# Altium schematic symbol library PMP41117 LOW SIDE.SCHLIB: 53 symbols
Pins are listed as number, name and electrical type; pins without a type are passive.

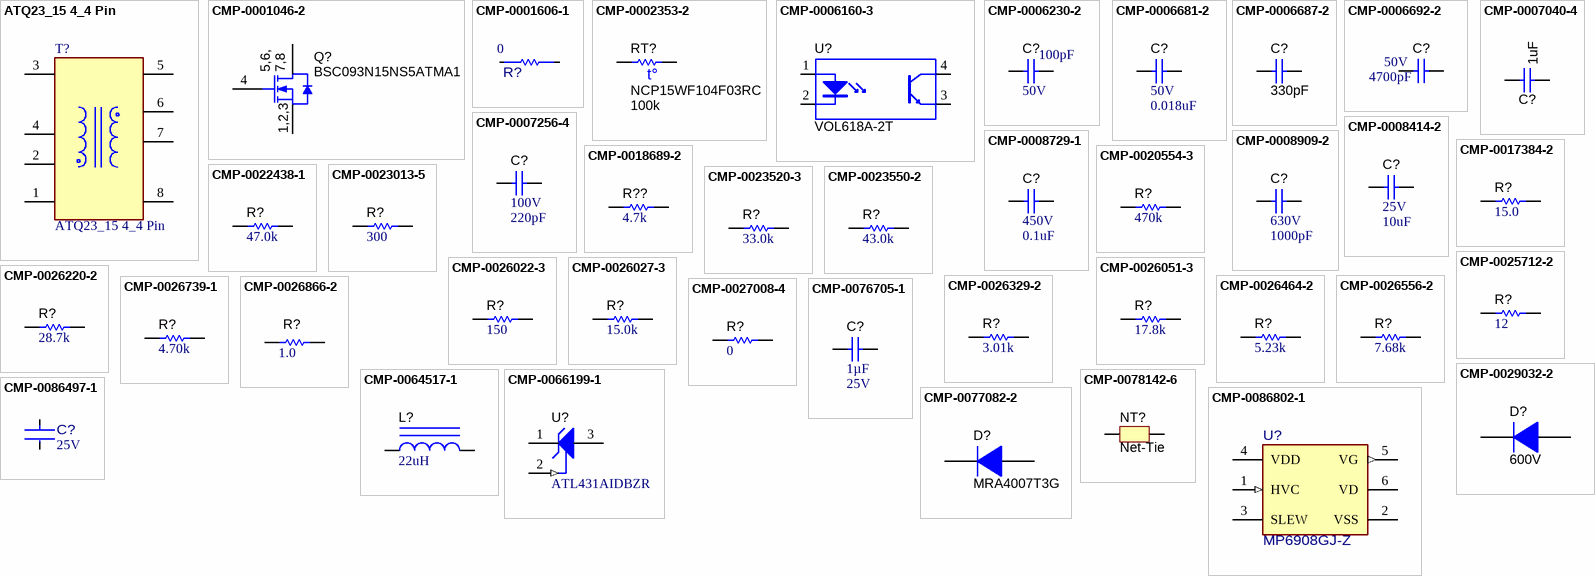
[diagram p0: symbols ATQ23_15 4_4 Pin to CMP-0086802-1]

## ATQ23_15 4_4 Pin
designator T?
footprint ATQ23.7_15 4+4 Pin
pins: 1, 2, 3, 4, 5, 6, 7, 8

## CMP-0001046-2
designator Q?, comment BSC093N15NS5ATMA1
MOSFET, N-CH, 150 V, 87 A, PG-TDSON-8; Alternate Manufacturer: None; Manufacturer: Infineon Technologies; SizeZ_mm: 1.12; ChType: N; Value2: 33 nC; VdsMax_V: 150V; SizeX_mm: 5.99; SizeY_mm: 4.9; Vgs_V: 20V; QgTyp_nC: 33; Value: 150V; SizeArea_mm2: 29.351; AEC Category: Q101; IdsMax_A: 87A; SizeAreaWB_mm2: 55.131; U/M: EA
footprint PG-TDSON-8 (Infineon recommended land pattern)
pins: 1 S, 2 S, 3 S, 4 G, 5 D, 6 D, 7 D, 8 D, 9 D

## CMP-0001606-1
designator R?, comment Res_ohm: 0  (hidden comment: CRCW04020000Z0EDHP)
RES Thick Film, 0Ω, 0.2W, 0402; Manufacturer: Vishay Dale; AEC Grade: Grade 0; AEC Qualified: Yes; Power_W: 200mW; SizeZ_mm: 0.4mm; VDC_V: 50V; Value: 0
footprint FP-CRCW04020000Z0EDHP_0402-MFG
footprint FP-CRCW04020000Z0EDHP_0402-IPC_C
footprint FP-CRCW04020000Z0EDHP_0402-IPC_B
footprint FP-CRCW04020000Z0EDHP_0402-IPC_A
pins: 1, 2

## CMP-0002353-2
designator RT?, comment NCP15WF104F03RC  value 100k
Thermistor NTC, 100k ohm, 1%, 0402; Manufacturer: MuRata; TaMax_C: 125°C; SizeX_mm: 1; SizeY_mm: 0.5; TaMin_C: -40°C; Power_W: 100mW; SizeZ_mm: 0.6; SizeAreaWB_mm2: 3; U/M: EA
footprint 0402S (Based on C0402S footprint from PADS legacy)
footprint 0402 (0402 from SM-752 data)
footprint 0402L (0402 from SM-752 data)
footprint 0402M (0402 from SM-752 data)
pins: 1, 2

## CMP-0006160-3
designator U?, comment VOL618A-2T
Optocoupler, 5 kV, 63-125% CTR, SMT; Manufacturer: Vishay-Semiconductor; CTR (Max): 125%; SizeAreaWB_mm2: 74.42; CTR (Min): 63%; SizeZ_mm: 2.3; SizeX_mm: 10.2; SizeY_mm: 4.1; SizeArea_mm2: 41.82; Voltage_Isolation_Vrms: 5kV
footprint SOP254P1020X230-4 (VISHAY)
pins: 1 A, 2 K, 3 E, 4 C
1 alternate drawing of the same symbol

## CMP-0006230-2
designator C?, comment VDC_V: 50V  ValueDisplayed: 100pF  (hidden comment: 885012205055)
CAP, CERM, 100 pF, 50 V, +/- 10%, X7R, 0402; Manufacturer: Wurth Elektronik; TaMin_C: -55°C; Polarized: N; SizeAreaWB_mm2: 3; Value1: Unknown; U/M: EA; Value: 100pF; TaMax_C: 125°C; SizeZ_mm: 0.6; SizeX_mm: 1; SizeY_mm: 0.5; Cap_Case: 0402; CompType: Capacitor; AEC Category: Q200
footprint 0402 (0402 from SM-752 data)
footprint 0402S (Based on C0402S footprint from PADS legacy)
footprint 0402L (0402 from SM-752 data)
footprint 0402M (0402 from SM-752 data)
pins: 1, 2

## CMP-0006681-2
designator C?, comment VDC_V: 50V  ValueDisplayed: 0.018uF  (hidden comment: GRM155R71H183KA12D)
CAP, CERM, 0.018 uF, 50 V, +/- 10%, X7R, 0402; Manufacturer: MuRata; TaMin_C: -55°C; Polarized: N; SizeAreaWB_mm2: 3; Value1: Unknown; U/M: EA; TaMax_C: 125°C; SizeZ_mm: 0.6; SizeX_mm: 1; SizeY_mm: 0.5; Cap_Case: 0402; CompType: Capacitor; Cap_F: 18nF; AEC Category: Q200
footprint 0402 (0402 from SM-752 data)
footprint 0402S (Based on C0402S footprint from PADS legacy)
footprint 0402L (0402 from SM-752 data)
footprint 0402M (0402 from SM-752 data)
pins: 1, 2

## CMP-0006687-2
designator C?, comment ValueDisplayed: 330pF  (hidden comment: GRM155R71H331KA01D)
CAP, CERM, 330 pF, 50 V, +/- 10%, X7R, 0402; Manufacturer: MuRata; TaMin_C: -55°C; Polarized: N; SizeAreaWB_mm2: 3; Value1: Unknown; U/M: EA; Value: 330pF; TaMax_C: 125°C; SizeZ_mm: 0.6; SizeX_mm: 1; SizeY_mm: 0.5; Cap_Case: 0402; Value2: 50V; CompType: Capacitor; AEC Category: Q200
footprint 0402 (0402 from SM-752 data)
footprint 0402S (Based on C0402S footprint from PADS legacy)
footprint 0402L (0402 from SM-752 data)
footprint 0402M (0402 from SM-752 data)
pins: 1, 2

## CMP-0006692-2
designator C?, comment VDC_V: 50V  ValueDisplayed: 4700pF  (hidden comment: GRM155R71H472KA01D)
CAP, CERM, 4700 pF, 50 V, +/- 10%, X7R, 0402; Manufacturer: MuRata; TaMin_C: -55°C; Polarized: N; SizeAreaWB_mm2: 3; Value1: Unknown; U/M: EA; Value: 4700pF; TaMax_C: 125°C; SizeZ_mm: 0.6; SizeX_mm: 1; SizeY_mm: 0.5; Cap_Case: 0402; CompType: Capacitor; Cap_F: 4.7nF; AEC Category: Q200
footprint 0402 (0402 from SM-752 data)
footprint 0402S (Based on C0402S footprint from PADS legacy)
footprint 0402L (0402 from SM-752 data)
footprint 0402M (0402 from SM-752 data)
pins: 1, 2

## CMP-0007040-4
designator C?, comment ValueDisplayed: 1uF  (hidden comment: C1608X7R1E105K080AB)
CAP, CERM, 1 µF, 25 V, +/- 10%, X7R, 0603; Manufacturer: TDK; Polarized: N; CompType: Capacitor; Value: 1uF; U/M: EA; Cap_F: 1µF; Value1: Unknown; VDC_V: 25V; TaMin_C: -55°C; TaMax_C: 125°C; Cap_Case: 0603; AEC Category: Q200; SizeArea_mm2: 1.28; SizeAreaWB_mm2: 4.68; SizeX_mm: 1.6; SizeY_mm: 0.8; SizeZ_mm: 1
footprint 0603 (0603 from SM-752 data)
footprint 0603_HV (Ernesto recommended land pattern.  26 mil between pads.)
footprint 0603L (0603 from SM-752 data)
footprint 0603S
footprint 0603M (0603 from SM-752 data)
pins: 1, 2

## CMP-0007256-4
designator C?, comment VDC_V: 100V  ValueDisplayed: 220pF  (hidden comment: GRM1885C2A221JA01D)
CAP, CERM, 220 pF, 100 V, +/- 5%, C0G/NP0, 0603; Manufacturer: MuRata; TaMin_C: -55°C; Polarized: N; SizeAreaWB_mm2: 4.68; Value1: Unknown; U/M: EA; Value: 220pF; TaMax_C: 125°C; SizeZ_mm: 1; SizeX_mm: 1.6; SizeY_mm: 0.8; Cap_Case: 0603; SizeArea_mm2: 1.28; CompType: Capacitor; AEC Category: Q200
footprint 0603 (0603 from SM-752 data)
footprint 0603_HV (Ernesto recommended land pattern.  26 mil between pads.)
footprint 0603L (0603 from SM-752 data)
footprint 0603S
footprint 0603M (0603 from SM-752 data)
pins: 1, 2

## CMP-0008414-2
designator C?, comment VDC_V: 25V  ValueDisplayed: 10uF  (hidden comment: TMK212BBJ106KG-T)
CAP, CERM, 10 uF, 25 V, +/- 10%, X5R, 0805; Manufacturer: Taiyo Yuden; TaMin_C: -55°C; Polarized: N; SizeAreaWB_mm2: 6.75; Value1: Unknown; U/M: EA; Value: 10uF; TaMax_C: 85°C; SizeZ_mm: 1.45; SizeX_mm: 2; SizeY_mm: 1.25; Cap_Case: 0805; SizeArea_mm2: 2.5; CompType: Capacitor; Cap_F: 10µF; AEC Category: Q200
footprint 0805_HV (0805 with 30mil clearance between pads)
footprint 0805M (0805 from SM-752 data)
footprint 0805 (0805 from SM-752 data)
footprint 0805L (0805 from SM-752 data)
footprint 0805_HV1 (Custom footprint based on analyzing multiple manufacturer recommendations)
pins: 1, 2

## CMP-0008729-1
designator C?, comment VDC_V: 450V  ValueDisplayed: 0.1uF  (hidden comment: C3216X7T2W104M160AA)
CAP, CERM, 0.1 uF, 450 V, +/- 20%, X7T, 1206; Manufacturer: TDK; TaMin_C: -55°C; Polarized: N; SizeAreaWB_mm2: 10.92; Value1: Unknown; U/M: EA; Value: 0.1uF; TaMax_C: 125°C; SizeZ_mm: 1.8; SizeX_mm: 3.2; SizeY_mm: 1.6; Cap_Case: 1206; SizeArea_mm2: 5.12; CompType: Capacitor; Cap_F: 100nF; AEC Category: Q200
footprint 1206_180
footprint 1206_180L (1206_180)
footprint 1206_180M (1206_180)
pins: 1, 2

## CMP-0008909-2
designator C?, comment VDC_V: 630V  ValueDisplayed: 1000pF  (hidden comment: GRM31BR72J102KW01L)
CAP, CERM, 1000 pF, 630 V, +/- 10%, X7R, 1206; Manufacturer: MuRata; TaMin_C: -55°C; Polarized: N; SizeAreaWB_mm2: 10.92; Value1: Unknown; U/M: EA; Value: 1000pF; TaMax_C: 125°C; SizeZ_mm: 1.35; SizeX_mm: 3.2; SizeY_mm: 1.6; Cap_Case: 1206; SizeArea_mm2: 5.12; CompType: Capacitor; Cap_F: 1nF; AEC Category: Q200
footprint 1206 (1206 from SM-752 data)
footprint 1206L (1206 from SM-752 data)
footprint 1206M (1206 from SM-752 data)
pins: 1, 2

## CMP-0017384-2
designator R?, comment ValueDisplayed: 15.0  (hidden comment: ERJ-8ENF15R0V)
RES, 15.0, 1%, 0.25 W, 1206; Manufacturer: Panasonic; Power_W: 250mW; TempCo: 100 ppm/C; Value_Code: 15R0; U/M: EA; Value: 15.0; EIA_Code: E96; Res_ohm: 15; SizeX_mm: 3.2; SizeY_mm: 1.6; SizeZ_mm: 1.35; Value2: 0.25W; SizeArea_mm2: 5.12; CompType: Resistor; VDC_V: 200V; AEC Category: Q200
footprint 1206 (1206 from SM-752 data)
footprint 1206L (1206 from SM-752 data)
footprint 1206M (1206 from SM-752 data)
pins: 1, 2

## CMP-0018689-2
designator R??, comment ValueDisplayed: 4.7k  (hidden comment: CRCW12064K70JNEA)
RES, 4.7 k, 5%, 0.25 W, 1206; Manufacturer: Vishay-Dale; Power_W: 250mW; TempCo: 200 ppm/C; Value_Code: 4k70; U/M: EA; Value: 4.7k; EIA_Code: E24; SizeX_mm: 3.2; SizeY_mm: 1.6; SizeZ_mm: 1.35; Value2: 0.25W; SizeArea_mm2: 5.12; CompType: Resistor; VDC_V: 200V; AEC Category: Q200
footprint 1206 (1206 from SM-752 data)
footprint 1206L (1206 from SM-752 data)
footprint 1206M (1206 from SM-752 data)
pins: 1, 2

## CMP-0020554-3
designator R?, comment ValueDisplayed: 470k  (hidden comment: CRCW0805470KJNEA)
RES, 470 k, 5%, 0.125 W, AEC-Q200 Grade 0, 0805; Manufacturer: Vishay-Dale; Power_W: 125mW; TempCo: 200 ppm/C; Value: 470k; EIA_Code: E24; SizeX_mm: 2; SizeY_mm: 1.25; SizeZ_mm: 1.45; Value2: 0.125W; SizeArea_mm2: 2.5; CompType: Resistor; AEC Qualified: Y; VDC_V: 150V; AEC Category: Q200; AEC Grade: 0
footprint 0805_HV (0805 with 30mil clearance between pads)
footprint 0805M (0805 from SM-752 data)
footprint 0805 (0805 from SM-752 data)
footprint 0805L (0805 from SM-752 data)
footprint 0805_HV1 (Custom footprint based on analyzing multiple manufacturer recommendations)
pins: 1, 2

## CMP-0022438-1
designator R?, comment ValueDisplayed: 47.0k  (hidden comment: CRCW060347K0FKEA)
RES, 47.0 k, 1%, 0.1 W, AEC-Q200 Grade 0, 0603; Manufacturer: Vishay-Dale; Power_W: 100mW; TempCo: 100 ppm/C; Value_Code: 47k0; U/M: EA; Value: 47.0k; Res_ohm: 47k; SizeX_mm: 1.6; SizeY_mm: 0.8; SizeZ_mm: 1; Value2: 0.1W; SizeArea_mm2: 1.28; CompType: Resistor; AEC Qualified: Y; VDC_V: 75V; AEC Grade: 0; AEC Category: Q200
footprint 0603 (0603 from SM-752 data)
footprint 0603_HV (Ernesto recommended land pattern.  26 mil between pads.)
footprint 0603L (0603 from SM-752 data)
footprint 0603S
footprint 0603M (0603 from SM-752 data)
pins: 1, 2

## CMP-0023013-5
designator R?, comment ValueDisplayed: 300  (hidden comment: RC0603FR-07300RL)
RES, 300, 1%, 0.1 W, 0603; Manufacturer: Yageo; Power_W: 100mW; TempCo: 100 ppm/C; Value_Code: 300R; Value: 300; SizeX_mm: 1.6; SizeY_mm: 0.8; SizeZ_mm: 1; Value2: 0.1W; SizeArea_mm2: 1.28; CompType: Resistor; AEC Qualified: N; VDC_V: 75V; AEC Category: Q200; SizeAreaWB_mm2: 4.68
footprint 0603 (0603 from SM-752 data)
footprint 0603_HV (Ernesto recommended land pattern.  26 mil between pads.)
footprint 0603L (0603 from SM-752 data)
footprint 0603S
footprint 0603M (0603 from SM-752 data)
pins: 1, 2

## CMP-0023520-3
designator R?, comment ValueDisplayed: 33.0k  (hidden comment: RG1608P-333-B-T5)
RES, 33.0 k, 0.1%, 0.1 W, 0603; Manufacturer: Susumu Co Ltd; Power_W: 100mW; TempCo: 25 ppm/C; Value_Code: 33k0; U/M: EA; Value: 33.0k; Res_ohm: 33k; SizeX_mm: 1.6; SizeY_mm: 0.8; SizeZ_mm: 1; Value2: 0.1W; SizeArea_mm2: 1.28; CompType: Resistor; VDC_V: 75V; AEC Category: Q200
footprint 0603 (0603 from SM-752 data)
footprint 0603_HV (Ernesto recommended land pattern.  26 mil between pads.)
footprint 0603L (0603 from SM-752 data)
footprint 0603S
footprint 0603M (0603 from SM-752 data)
pins: 1, 2

## CMP-0023550-2
designator R?, comment ValueDisplayed: 43.0k  (hidden comment: RG1608P-433-B-T5)
RES, 43.0 k, 0.1%, 0.1 W, 0603; Manufacturer: Susumu Co Ltd; Power_W: 100mW; TempCo: 25 ppm/C; Value_Code: 43k0; U/M: EA; Value: 43.0k; Res_ohm: 43k; SizeX_mm: 1.6; SizeY_mm: 0.8; SizeZ_mm: 1; Value2: 0.1W; SizeArea_mm2: 1.28; CompType: Resistor; VDC_V: 75V; AEC Category: Q200
footprint 0603 (0603 from SM-752 data)
footprint 0603_HV (Ernesto recommended land pattern.  26 mil between pads.)
footprint 0603L (0603 from SM-752 data)
footprint 0603S
footprint 0603M (0603 from SM-752 data)
pins: 1, 2

## CMP-0025712-2
designator R?, comment ValueDisplayed: 12  (hidden comment: CRCW060312R0JNEA)
RES, 12, 5%, 0.1 W, 0603; Manufacturer: Vishay-Dale; Power_W: 100mW; TempCo: 200 ppm/C; Value_Code: 12R0; U/M: EA; Value: 12; EIA_Code: E24; SizeX_mm: 1.6; SizeY_mm: 0.8; SizeZ_mm: 1; Value2: 0.1W; SizeArea_mm2: 1.28; CompType: Resistor; VDC_V: 75V; AEC Category: Q200
footprint 0603 (0603 from SM-752 data)
footprint 0603_HV (Ernesto recommended land pattern.  26 mil between pads.)
footprint 0603L (0603 from SM-752 data)
footprint 0603S
footprint 0603M (0603 from SM-752 data)
pins: 1, 2

## CMP-0026022-3
designator R?, comment ValueDisplayed: 150  (hidden comment: CRCW0402150RFKED)
RES, 150, 1%, 0.063 W, AEC-Q200 Grade 0, 0402; Manufacturer: Vishay-Dale; Power_W: 63mW; TempCo: 100 ppm/C; Value_Code: 150R; Value: 150; EIA_Code: E96; SizeX_mm: 1; SizeY_mm: 0.5; SizeZ_mm: 0.6; Value2: 0.063W; CompType: Resistor; AEC Qualified: Y; VDC_V: 50V; AEC Category: Q200; AEC Grade: 0
footprint 0402 (0402 from SM-752 data)
footprint 0402S (Based on C0402S footprint from PADS legacy)
footprint 0402L (0402 from SM-752 data)
footprint 0402M (0402 from SM-752 data)
pins: 1, 2

## CMP-0026027-3
designator R?, comment ValueDisplayed: 15.0k  (hidden comment: CRCW040215K0FKED)
RES, 15.0 k, 1%, 0.063 W, AEC-Q200 Grade 0, 0402; Manufacturer: Vishay-Dale; Power_W: 63mW; TempCo: 100 ppm/C; Value_Code: 15k0; Value: 15.0k; EIA_Code: E96; Res_ohm: 15k; SizeX_mm: 1; SizeY_mm: 0.5; SizeZ_mm: 0.6; Value2: 0.063W; CompType: Resistor; AEC Qualified: Y; VDC_V: 50V; AEC Category: Q200; AEC Grade: 0
footprint 0402 (0402 from SM-752 data)
footprint 0402S (Based on C0402S footprint from PADS legacy)
footprint 0402L (0402 from SM-752 data)
footprint 0402M (0402 from SM-752 data)
pins: 1, 2

## CMP-0026051-3
designator R?, comment ValueDisplayed: 17.8k  (hidden comment: CRCW040217K8FKED)
RES, 17.8 k, 1%, 0.063 W, AEC-Q200 Grade 0, 0402; Manufacturer: Vishay-Dale; Power_W: 63mW; TempCo: 100 ppm/C; Value_Code: 17k8; Value: 17.8k; EIA_Code: E96; SizeX_mm: 1; SizeY_mm: 0.5; SizeZ_mm: 0.6; Value2: 0.063W; CompType: Resistor; AEC Qualified: Y; VDC_V: 50V; AEC Category: Q200; AEC Grade: 0
footprint 0402 (0402 from SM-752 data)
footprint 0402S (Based on C0402S footprint from PADS legacy)
footprint 0402L (0402 from SM-752 data)
footprint 0402M (0402 from SM-752 data)
pins: 1, 2

## CMP-0026220-2
designator R?, comment ValueDisplayed: 28.7k  (hidden comment: CRCW040228K7FKED)
RES, 28.7 k, 1%, 0.063 W, AEC-Q200 Grade 0, 0402; Manufacturer: Vishay-Dale; Power_W: 63mW; TempCo: 100 ppm/C; Value_Code: 28k7; Value: 28.7k; EIA_Code: E96; SizeX_mm: 1; SizeY_mm: 0.5; SizeZ_mm: 0.6; Value2: 0.063W; CompType: Resistor; AEC Qualified: Y; VDC_V: 50V; AEC Category: Q200; AEC Grade: 0
footprint 0402 (0402 from SM-752 data)
footprint 0402S (Based on C0402S footprint from PADS legacy)
footprint 0402L (0402 from SM-752 data)
footprint 0402M (0402 from SM-752 data)
pins: 1, 2

## CMP-0026329-2
designator R?, comment ValueDisplayed: 3.01k  (hidden comment: CRCW04023K01FKED)
RES, 3.01 k, 1%, 0.063 W, AEC-Q200 Grade 0, 0402; Manufacturer: Vishay-Dale; Power_W: 63mW; TempCo: 100 ppm/C; Value_Code: 3k01; Value: 3.01k; EIA_Code: E96; SizeX_mm: 1; SizeY_mm: 0.5; SizeZ_mm: 0.6; Value2: 0.063W; CompType: Resistor; AEC Qualified: Y; VDC_V: 50V; AEC Category: Q200; AEC Grade: 0
footprint 0402 (0402 from SM-752 data)
footprint 0402S (Based on C0402S footprint from PADS legacy)
footprint 0402L (0402 from SM-752 data)
footprint 0402M (0402 from SM-752 data)
pins: 1, 2

## CMP-0026464-2
designator R?, comment ValueDisplayed: 5.23k  (hidden comment: CRCW04025K23FKED)
RES, 5.23 k, 1%, 0.063 W, AEC-Q200 Grade 0, 0402; Manufacturer: Vishay-Dale; Power_W: 63mW; TempCo: 100 ppm/C; Value_Code: 5k23; Value: 5.23k; EIA_Code: E96; SizeX_mm: 1; SizeY_mm: 0.5; SizeZ_mm: 0.6; Value2: 0.063W; CompType: Resistor; AEC Qualified: Y; VDC_V: 50V; AEC Category: Q200; AEC Grade: 0
footprint 0402 (0402 from SM-752 data)
footprint 0402S (Based on C0402S footprint from PADS legacy)
footprint 0402L (0402 from SM-752 data)
footprint 0402M (0402 from SM-752 data)
pins: 1, 2

## CMP-0026556-2
designator R?, comment ValueDisplayed: 7.68k  (hidden comment: CRCW04027K68FKED)
RES, 7.68 k, 1%, 0.063 W, AEC-Q200 Grade 0, 0402; Manufacturer: Vishay-Dale; Power_W: 63mW; TempCo: 100 ppm/C; Value_Code: 7k68; Value: 7.68k; EIA_Code: E96; SizeX_mm: 1; SizeY_mm: 0.5; SizeZ_mm: 0.6; Value2: 0.063W; CompType: Resistor; AEC Qualified: Y; VDC_V: 50V; AEC Category: Q200; AEC Grade: 0
footprint 0402 (0402 from SM-752 data)
footprint 0402S (Based on C0402S footprint from PADS legacy)
footprint 0402L (0402 from SM-752 data)
footprint 0402M (0402 from SM-752 data)
pins: 1, 2

## CMP-0026739-1
designator R?, comment ValueDisplayed: 4.70k  (hidden comment: RC0402FR-074K7L)
RES, 4.70 k, 1%, 0.0625 W, 0402; Manufacturer: Yageo America; Power_W: 62.5mW; TempCo: 100 ppm/C; Value_Code: 4k70; U/M: EA; Value: 4.70k; Res_ohm: 4.7k; SizeX_mm: 1; SizeY_mm: 0.5; SizeZ_mm: 0.6; CompType: Resistor; AEC Qualified: N; VDC_V: 50V; AEC Category: Q200
footprint 0402 (0402 from SM-752 data)
footprint 0402S (Based on C0402S footprint from PADS legacy)
footprint 0402L (0402 from SM-752 data)
footprint 0402M (0402 from SM-752 data)
pins: 1, 2

## CMP-0026866-2
designator R?, comment ValueDisplayed: 1.0  (hidden comment: CRCW04021R00JNED)
RES, 1.0, 5%, 0.063 W, 0402; Manufacturer: Vishay-Dale; Power_W: 63mW; TempCo: 200 ppm/C; Value_Code: 1R00; U/M: EA; Value: 1.0; EIA_Code: E24; Res_ohm: 1; SizeY_mm: 0.5; SizeZ_mm: 0.6; Value2: 0.063W; CompType: Resistor; VDC_V: 50V; AEC Category: Q200
footprint 0402 (0402 from SM-752 data)
footprint 0402S (Based on C0402S footprint from PADS legacy)
footprint 0402L (0402 from SM-752 data)
footprint 0402M (0402 from SM-752 data)
pins: 1, 2

## CMP-0027008-4
designator R?, comment ValueDisplayed: 0  (hidden comment: CRCW02010000Z0ED)
RES, 0, 5%, 0.05 W, 0201; Manufacturer: Vishay-Dale; Power_W: 50mW; TempCo: ppm/C; Value_Code: 0000; Value: 0; EIA_Code: E24; SizeX_mm: 0.6; SizeY_mm: 0.3; SizeZ_mm: 0.26; Value2: 0.05W; SizeArea_mm2: 0.18; CompType: Resistor; AEC Qualified: N; AEC Category: Q200
footprint 0201 (Data from Kemet datasheet CC101_COM dated 7/28/11)
footprint 0201_Silk (Data from Kemet datasheet CC101_COM dated 7/28/11)
footprint 0201L (Data from Kemet datasheet CC101_COM dated 7/28/11)
footprint 0201M (Data from Kemet datasheet CC101_COM dated 7/28/11)
pins: 1, 2

## CMP-0029032-2
designator D?, comment value 600V  (hidden comment: ES1JFL)
Diode, Switching, 600 V, 1 A, SOD-123; Manufacturer: ON Semiconductor; SizeY_mm: 1.7; Io_A: 1A; SizeAreaWB_mm2: 13.095; SizeArea_mm2: 6.545; Vf_V: 1V; TJmax_C: 150°C; SizeX_mm: 3.85; SizeZ_mm: 1.35; Green_Lifecycle: Active; Green_REACh: Passed
footprint SOD-123 (On Semi recommended land pattern)
pins: 1 K, 2 A

## CMP-0064517-1
designator L?, comment ValueDisplayed: 22uH  (hidden comment: 7447462220)
Inductor, Unshielded Drum Core, Ferrite, 22 uH, 1.7 A, 0.102 ohm, TH; Manufacturer: Wurth Elektronik; Isat: 1.7A @ 10% inductance drop; Irms: 1.8A @ 40C rise; Green_Lifecycle: Active; SizeAreaWB_mm2: 64; DCR_ohm: 0.102; Green_REACh: Passed; Value: 22uH; Imax_A: 1.7A; SizeZ_mm: 8.5; SizeX_mm: 6; SizeArea_mm2: 36; Ind_H: 22µH; AEC Category: Q200
footprint WE-TI_5075 (Wurth WE-TI 5075)
pins: 1, 2

## CMP-0066199-1
designator U?, comment ATL431AIDBZR
2.5V Low Iq Adjustable Precision Shunt Regulator, DBZ0003A (SOT-23-3); Alternate Manufacturer: Texas Instruments; SizeAreaWB_mm2: 14.0; U/M: EA; SizeZ_mm: 1.12; SizeX_mm: 2.5; SizeY_mm: 3.0; SizeArea_mm2: 7.5; CompType: IC
footprint DBZ0003A_N (SOT23, 3-Leads, Body 2.9x1.3mm, Pitch 0.95mm, Lead Span 2.4mm, IPC Medium Density)
footprint DBZ0003A_L (SOT23, 3-Leads, Body 2.9x1.3mm, Pitch 0.95mm, Lead Span 2.4mm, IPC High Density)
footprint DBZ0003A_M (SOT23, 3-Leads, Body 2.9x1.3mm, Pitch 0.95mm, Lead Span 2.4mm, IPC Low Density)
pins: 1 CATHODE, 2 REF (in), 3 ANODE

## CMP-0076705-1
designator C?, comment Cap_F: 1µF  VDC_V: 25V  (hidden comment: CGA3E1X7R1E105K080AC)
CAP, CERM, 1 µF, 25 V,+/- 10%, X7R, AEC-Q200 Grade 1, 0603; Manufacturer: TDK; SizeAreaWB_mm2: 4.68; SizeArea_mm2: 1.28; AEC Qualified: Y; AEC Category: Q200; Value: 1uF; TaMax_C: 125°C; SizeZ_mm: 1.0; AEC Grade: 1; Polarized: N; TaMin_C: -55°C; SizeY_mm: 0.8; U/M: EA; CompType: Capacitor; SizeX_mm: 1.6; Cap_Case: 1.6x0.8x0.8mm
footprint 0603S
footprint 0603_HV (Ernesto recommended land pattern.  26 mil between pads.)
footprint 0603L (0603 from SM-752 data)
footprint 0603M (0603 from SM-752 data)
footprint 0603 (0603 from SM-752 data)
pins: 1, 2

## CMP-0077082-2
designator D?, comment MRA4007T3G
Diode, Standard Recovery Rectifier, 1000 V, 1 A, AEC-Q101, SMA; Manufacturer: ON Semiconductor; Value2: 1.1V; TJmax_C: 175°C; SizeX_mm: 5.59; Green_Lifecycle: Active; Value1: 1A; Green_REACh: Passed; AEC Qualified: Y; AEC Category: Q101; SizeArea_mm2: 16.3228; SizeY_mm: 2.92; SizeAreaWB_mm2: 37.3428; Value: 1000V; RJC_CperW: 16.2; SizeZ_mm: 2.87; Vr_V: 1kV
footprint SMA (Molded Diode, 2-Leads, Body 4.3x2.6mm, IPC Medium Density, based on OnSemi component dimensions and land pattern)
pins: 1 K, 2 A

## CMP-0078142-6
designator NT?, comment Net-Tie  (net tie, no BOM)
Single point connection between nets.
footprint Net-Tie_0805_HV_NoOverlay (0805_HV pads tied by 10mil copper trace which can be cut.  An 0805 part can be placed on pads.)
footprint Net-Tie_10milWide_30milLong (10mil net tie, no solder mask opening, no solder paste)
footprint NetTie_0402 (Net Tie 0402 size)
footprint Net-Tie_50milWide_30milLong (50mil net tie, no solder mask opening, no solder paste)
footprint Net-Tie_20milWide_60milLong (20mil net tie, no solder mask opening, no solder paste)
footprint Net-Tie_6mil (10mil net tie, no solder mask opening, no solder paste)
footprint NetTie_1206_NoOverlay (1206 pads tied by 10mil copper trace which can be cut.  Part can be placed on pads.)
footprint Net-Tie_0805_HV (0805_HV pads tied by 10mil copper trace which can be cut.  An 0805 part can be placed on pads.)
footprint NetTie_1206 (1206 pads tied by 10mil copper trace which can be cut.  Part can be placed on pads.)
footprint Net-Tie_5milWide_60milLong (5mil net tie, no solder mask opening, no solder paste)
footprint NetTie_0603 (Net Tie 0603 size)
footprint Net-Tie_4x6mil
footprint Net-Tie_6x8mil
footprint Net-Tie_4milsWide_10milsLong (Net-Tie 4 mils wide by 10 mils long)
footprint Net-Tie6milsWide_20milsLong (6 mils wide by 20 mils long)
footprint Net-Tie7milsWide_20milsLong (7 mils wide by 20 mils long)
footprint Net-Tie_10mil (10mil net tie, no solder mask opening, no solder paste)
pins: 1, 2

## CMP-0086497-1
designator C?, comment VDC_V: 25V  (hidden comment: CGA3E2X8R1E104K080AD)
0.1µF ±10% 25V Ceramic Capacitor X8R 0603 (1608 Metric); Manufacturer: TDK Corporation; SizeZ_mm: 0.95mm; Cap_F: 100nF; TempCo: 15%; AEC Grade: Grade 0; AEC Qualified: Yes; Symbol Name: SYM-CGA3E2X8R1E104K080AD
footprint FP-CGA3E2X8R1E104K080AD_0603-MFG
footprint FP-CGA3E2X8R1E104K080AD_0603-IPC_C
footprint FP-CGA3E2X8R1E104K080AD_0603-IPC_B
footprint FP-CGA3E2X8R1E104K080AD_0603-IPC_A
pins: 1, 2

## CMP-0086802-1
designator U?, comment MP6908GJ-Z
FAST TURN-OFF INTELLIGENT RECTIF; Manufacturer: Monolithic Power Systems; SizeZ_mm: 1mm; Symbol Name: SYM-MP6908GJ-Z
footprint FP-MP6908GJ-Z_TSOT23-6-MFG
footprint FP-MP6908GJ-Z_TSOT23-6-IPC_C
footprint FP-MP6908GJ-Z_TSOT23-6-IPC_B
footprint FP-MP6908GJ-Z_TSOT23-6-IPC_A
pins: 1 HVC (in), 2 VSS (power), 3 SLEW, 4 VDD (power), 5 VG (out), 6 VD (hiz)

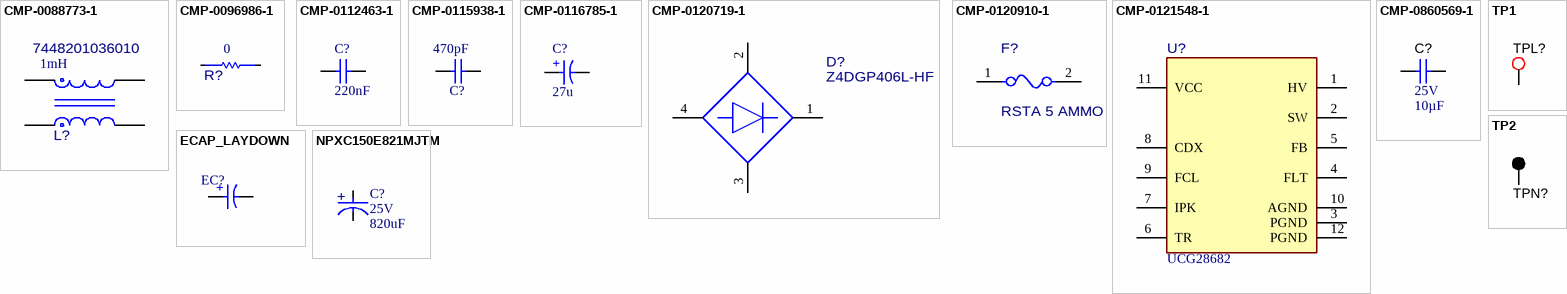
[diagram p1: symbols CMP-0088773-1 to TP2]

## CMP-0088773-1
designator L?, comment 7448201036010  Ind_H: 1mH
Common Mode Power Line Choke; Manufacturer: Wurth Electronics; Imax_A: 3.6A; AEC Qualified: No; Tolerance_%: 30%; Test Frequency: 10kHz; DCR_ohm: 36m; SizeZ_mm: 20.2mm
footprint L-T8*5
pins: 1, 2, 3, 4

## CMP-0096986-1
designator R?, comment value 0  (hidden comment: RCC12060000Z0EA)
Res Jumper Thick Film 1206 0 Ohm Molded Paper T/R; Manufacturer: Vishay Dale; AEC Qualified: Yes; SizeZ_mm: 0.6mm; AEC Grade: Grade 0; Power_W: 500mW; VDC_V: 200V
footprint FP-RCC12060000Z0EA_1206-MFG
footprint FP-RCC12060000Z0EA_1206-IPC_C
footprint FP-RCC12060000Z0EA_1206-IPC_B
footprint FP-RCC12060000Z0EA_1206-IPC_A
pins: 1, 2

## CMP-0112463-1
designator C?, comment Cap_F: 220nF  (hidden comment: 890324023028)
WCAP-FTX2 Film Capacitor, THT, L13 x W8 x H14mm, 220nF, 275V; Manufacturer: Wurth Elektronik; Capacitance Tolerance: +/-10%; Dissipation Factor @100kHz: 2%; Dissipation Factor @10kHz: 0.2%; Dissipation Factor @1kHz: 0.1%; Insulation Resistance: 30000MOhm; Pitch: 10mm; Rate of Voltage Rise: 300V/us; Technical Reference: MX2P010224K275ASPB16000
footprint WCAP-FTX2_L13W8H14 (Film Capacitors, 13x8x14mm)
footprint XCAP
pins: 1, 2

## CMP-0115938-1
designator C?, comment Cap_F: 470pF  (hidden comment: 885362210009)
WCAP-CSSA Multilayer Ceramic Chip Safety Capacitor, size 1808, X7R Class II, 470pF, 250VAC; Manufacturer: Wurth Elektronik; Capacitance Tolerance: +/-10%; Case/Size Code: 1808; Dissipation Factor: 2.5%; Impulse Voltage: 2500VDC; Insulation Resistance: 10GOhm; Rated Voltage (AC): 250V; Safety Class: X2; Technical Reference: X7R1808471KB50IFCT10000
footprint WCAP-CSSA_1808_L4.5W2H1.6 (Ceramic Capacitors, body 4.50x2.00mm)
pins: 1, 2

## CMP-0116785-1
designator C?, comment 27u
WCAP-ATG5 Aluminum Electrolytic Capacitor, Radial, THT, D8 x H16mm, 22µF, 400V; Manufacturer: Wurth Elektronik; Manufacturer Part Number: 860021374027; Capacitance Tolerance: +0%/-40%; Dissipation Factor: 15%; Endurance: 2000h; Leakage Current: 264uA; Ripple Current: 200mA; Technical Reference: ATJE1602203400DSPA7B0LR
footprint WCAP-ATG5_D8H16 (Aluminum Electrolytic Capacitors, 8x16mm)
pins: 1 P, 2 N

## CMP-0120719-1
designator D?, comment Z4DGP406L-HF
Bridge Rectifier Single Phase Standard 600 V Surface Mount Z4-D; Manufacturer: Comchip; AEC Qualified: No; SizeZ_mm: 1.45mm; TJmax_C: 175°C; Vf_V: 600V; Cap_F: 45pF; Forward Current: 4A; Max Surge Forward Current: 150A; Peak Reverse Current: 0.08uA
footprint FP-Z4DGP406L-HF_SMT_8MM1_10MM5-MFG
pins: 1 +, 2 1_~, 3 2_~, 4 -

## CMP-0120910-1
designator F?, comment RSTA 5 AMMO
5 A 250 V AC 63 V DC Fuse Board Mount (Cartridge Style Excluded) Through Hole Radial, Box; Manufacturer: Bel Fuse; Interrupt_AC: 100A; MeltingTyp: 94A2Sec; SizeZ_mm: 8.1mm; VAC_V: 277V; VDC_V: 63V; Fuse Speed: Slow; AEC Grade: Grade 1; AEC Qualified: Yes; Fuse Current: 5A; Fuse Voltage Drop: 0.075V; Res_ohm: 0.009Ω; Standoff Height: 0.5mm
footprint FP-RSTA 5 AMMO_RADIAL-MFG
footprint FUSE
pins: 1, 2

## CMP-0121548-1
designator U?, comment UCG28682
Manufacturer: Texas Instruments; SizeZ_mm: 1mm; Standoff Height: 0mm
footprint REZ0012A-MFG
pins: 1 HV (power), 2 SW (power), 3 PGND (power), 4 FLT, 5 FB, 6 TR, 7 IPK, 8 CDX, 9 FCL, 10 AGND (power), 11 VCC (power), 12 PGND (power)

## CMP-0860569-1
designator C?, comment VDC_V: 25V  ValueDisplayed: 10µF  (hidden comment: GRM188R61E106KA73D)
CAP, CERM, 10 µF, 25 V,+/- 10%, X5R, 0603; Manufacturer: MuRata; SizeZ_mm: 1; AEC Category: Q200; AEC Qualified: N; TaMin_C: -55°C; Cap_Case: 0603; SizeY_mm: 0.8; SizeAreaWB_mm2: 4.68; SizeArea_mm2: 1.28; TaMax_C: 85°C; SizeX_mm: 1.6; Value: 10uF; CompType: Capacitor; U/M: EA
footprint 0603 (0603 from SM-752 data)
footprint 0603M (0603 from SM-752 data)
footprint 0603L (0603 from SM-752 data)
footprint 0603_HV (Ernesto recommended land pattern.  26 mil between pads.)
footprint 0603S
pins: 1, 2

## ECAP_LAYDOWN
designator EC?  (value not drawn)
25V/470uF D5.5*11mm; Value: 470uF; Voltage: 25V
footprint CE05.5P254L11
pins: 1 P, 2 N

## NPXC150E821MJTM
designator C?, comment value 820uF  Voltage: 25V  (hidden comment: 25V 820uF)
CAP, 25V 820uF D6.3X15mm
footprint Ecap 6.3_15_2.5
pins: 1 CATHODE, 2 ANODE

## TP1
designator TPL?  (value not drawn)
Test Point, Multipurpose, Red, TH; Manufacturer: Keystone; PartNumber: 5012; CNHeader: FALSE; Green_Lifecycle: Active; Green_REACh: Passed; ContactFinish: Silver; CT: TRUE
footprint Keystone5012 (Keystone Multipurpose loops)
footprint Test Point
pins: 1

## TP2
designator TPN?, comment NEUTRAL  (value not drawn)
Test Point, Multipurpose, Black, TH; Manufacturer: Keystone; PartNumber: 5011; CNHeader: FALSE; Green_Lifecycle: Active; Green_REACh: Passed; ContactFinish: Silver; CT: TRUE
footprint Test Point
pins: 1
